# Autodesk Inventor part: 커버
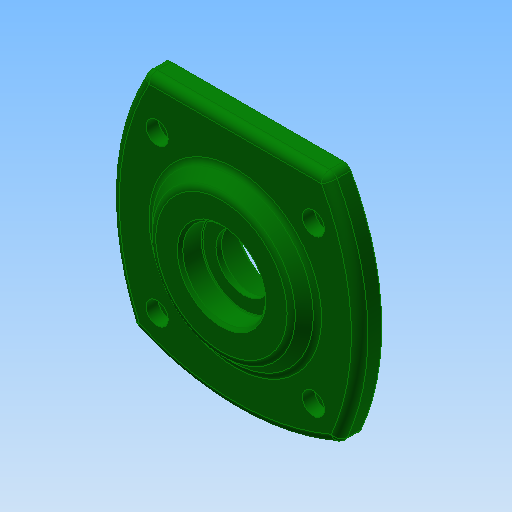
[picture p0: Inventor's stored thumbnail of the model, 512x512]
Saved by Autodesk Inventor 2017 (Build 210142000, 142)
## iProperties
Created: 2016-05
Part Number: 커버
Document SubType Name: Modeling
Designer: mduedu
Density: 2.71 g/cm^3
Material: 알루미늄 6061
Appearance: 진녹색
Author: mduedu
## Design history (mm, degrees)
sketch "스케치1"
  geometry: L1 (0, 0)-(-37.029, 37.029); L2 (0, 0)-(0, 45); L3 (0, 0)-(45, 0); L4 (32.942, 45)-(-32.942, 45); C1 r 25 at (0, 0); A1 r 90 centre (45, 0) between (-32.942, 45) and (-37.029, -37.029); A2 r 90 centre (0, 45) between (-37.029, -37.029) and (37.029, -37.029); A3 r 90 centre (-45, 0) between (37.029, -37.029) and (32.942, 45); 2 further points
  constraints: 9 point on circle, 8 end point, 4 centre point, 2 horizontal alignment, 2 vertical alignment, 1 coincident, 1 equal radius, 1 horizontal, 1 midpoint, 1 parallel, 1 other
  dimensions: "d28" = 90 distance between centres of A3 A1; "d30" = 50 diameter of C1; "d31" = 45 deg angle of L2 L1; "d33" = 90 distance from line of L4 point (0, -45); "d35" = 45 distance from line of L4 A1.centre (= 0.5 x d33); "d36" = 45 distance from line of L2 A1.centre (= 0.5 x d28)
extrude "돌출1" new body sketch "스케치1" distance "d0" = 8; taper "d1" = 0 deg
extrude "돌출2" join sketch "스케치1" distance "d2" = 12; taper "d3" = 0 deg
sketch "스케치2"
  geometry: C1 r 30 at (0, 0); 1 further point
  constraints: 1 centre point, 1 coincident
  dimensions: "d4" = 60 diameter of C1
extrude "돌출3" join sketch "스케치2" distance "d5" = 5; taper "d6" = -45 deg
sketch "스케치3"
  geometry: C1 r 1.621 at (-28.284, 28.284) reference; C2 r 1.621 at (28.284, 28.284) reference; C3 r 1.621 at (28.284, -28.284) reference; C4 r 1.621 at (-28.284, -28.284) reference; 1 further point
hole "구멍1" sketch "스케치3" at (28.284, 28.284), (-28.284, 28.284), (-28.284, -28.284), (28.284, -28.284) diameter "d7" = 4.5; stored, may be unused: countersink angle "d11" = 90 deg, drill point angle "d13" = 118 deg; dims "d8" = 6, "d9" = 8, "d10" = 4.4, "d12" = 8
fillet "모깎기1" dims "d14" = 3
sketch "스케치4"
  geometry: L1 (-23.757, 13)-(23.757, 13) reference; L2 (25, -12)-(-25, -12) reference; L3 (0, -12)-(0, 13); L4 (-20, -12)-(-20, 0); L5 (-20, 0)-(-15, 0); L6 (-15, 0)-(-15, 3); L7 (-15, 3)-(-10, 3); L8 (-10, 3)-(-10, 5); L9 (-10, 5)-(-15, 5); L10 (-15, 5)-(-15, 13); 1 further point
  constraints: 16 end point, 6 parallel, 2 midpoint, 2 point on line, 1 perpendicular
  dimensions: "d15" = 40 diameter of L4 L3; "d16" = 30 diameter of L10 L3; "d17" = 8 distance of L9.end L10.end; "d18" = 12 distance of L4.start L4.end; "d19" = 3 distance of L5.end L6.end; "d20" = 30 diameter of L6 L3; "d21" = 20 diameter of L8 L3
revolve "회전1" sketch "스케치4" stored, may be unused: angle "d22" = 90 deg
fillet "모깎기2" dims "d23" = 3
fillet "모깎기3" dims "d24" = 0.3
chamfer "모따기1" distance "d25" = 1; stored, may be unused: second distance "d26" = 2, angle "d27" = 45 deg
node "솔리드1"
node "참조2"
node "참조3"
node "참조4"
node "참조5"
